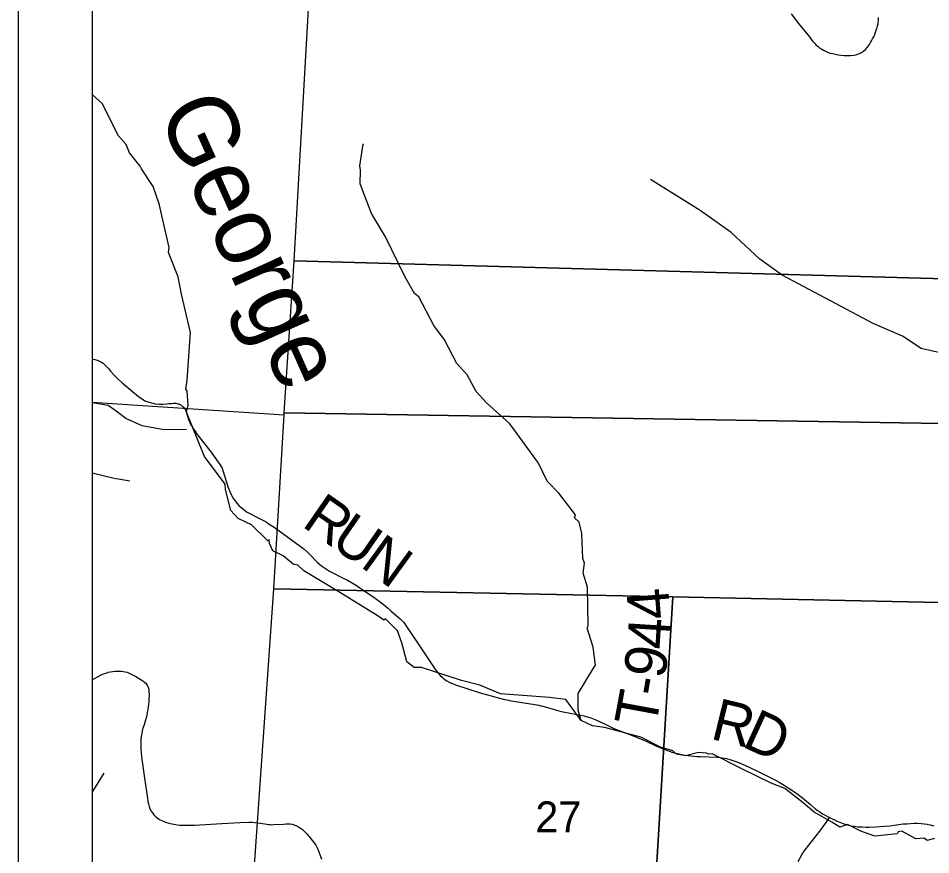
# Model space of a CAD drawing. Extents: x -2.1 to 31.9, y 6.3 to 28.3.
# Drawn here: x -0.066 to 1.171, y 22.391 to 23.525 of the extents above; entities that cross this region are included whole.
import ezdxf

# ---------------------------------------------------------------- set-up
doc = ezdxf.new("R2010")
doc.units = 0
for name, color, linetype in [('Default', 7, 'Continuous'), ('GM_X_County_Road', 7, 'Continuous'), ('GM_X_County_Road_Text', 7, 'Continuous'), ('GM_X_Minor_River', 7, 'Continuous'), ('GM_X_Minor_River_Text', 7, 'Continuous'), ('GM_X_Section', 7, 'Continuous'), ('GM_X_Section_Text', 7, 'Continuous'), ('GM_X_Township_Road', 7, 'Continuous'), ('GM_X_Township_Road_Text', 7, 'Continuous'), ('SH_Cut_Line', 7, 'Continuous'), ('SH_Data', 7, 'Continuous')]:
    doc.layers.add(name, color=color, linetype=linetype)

msp = doc.modelspace()

# ---------------------------------------------------------------- linework, layer by layer
at = {"layer": 'Default'}
for points in [[(0.0344, 26.1105), (0.0344, 20.444), (3.7533, 20.444), (3.8489, 20.5389), (3.9894, 20.6326), (4.16, 20.7203), (4.2895, 20.7662), (4.3023, 20.7658), (4.3091, 20.8714), (4.3751, 21.8979), (4.4168, 22.5238), (4.4383, 22.8067), (4.4651, 23.2405), (4.4901, 23.6442), (4.5473, 24.5954), (4.5667, 24.9084), (4.6032, 25.4816), (4.6286, 25.8765), (3.8625, 25.9158), (3.0763, 25.9555), (2.8034, 25.9683), (2.0757, 26.0047), (0.4641, 26.0883)], [(0.0344, 24.0467), (0.0344, 23.0048), (0.2947, 22.9877), (0.2949, 22.9906), (0.3083, 23.1964), (0.3317, 23.6098), (0.3588, 24.0351)]]:
    msp.add_lwpolyline(points, close=True, dxfattribs=at)
at = {"layer": 'GM_X_County_Road'}
for points in [[(0.0344, 23.0636), (0.0384, 23.0625), (0.0416, 23.0616), (0.0447, 23.0606), (0.0472, 23.0592), (0.0494, 23.0576), (0.0519, 23.0555), (0.0546, 23.0527), (0.057, 23.0501), (0.0596, 23.047), (0.0639, 23.0419), (0.0667, 23.039), (0.0695, 23.0364), (0.0755, 23.0313), (0.0976, 23.0127), (0.1022, 23.0094), (0.1062, 23.0069), (0.1102, 23.0054), (0.115, 23.0039), (0.1202, 23.0028), (0.1255, 23.0023), (0.1305, 23.0022), (0.1353, 23.0025), (0.1392, 23.0029), (0.1424, 23.0031), (0.1446, 23.0033), (0.1461, 23.0033), (0.1478, 23.0033), (0.1492, 23.0031), (0.1508, 23.0028), (0.1521, 23.0024), (0.1535, 23.0018), (0.1547, 23.0012), (0.1558, 23.0004), (0.1568, 22.9996), (0.1577, 22.9988), (0.1586, 22.9979), (0.1593, 22.9971), (0.1606, 22.9953), (0.1612, 22.9942), (0.1617, 22.993), (0.1625, 22.9909), (0.1631, 22.9884), (0.1637, 22.9858), (0.1646, 22.983), (0.1657, 22.9802), (0.167, 22.9772), (0.1685, 22.9741), (0.1704, 22.9708), (0.1725, 22.9677), (0.1747, 22.9645), (0.1771, 22.9611), (0.1957, 22.9369), (0.2063, 22.9222), (0.208, 22.9198), (0.2095, 22.9176), (0.2106, 22.9153), (0.2119, 22.9122), (0.2191, 22.8893), (0.2213, 22.8836), (0.2231, 22.8795), (0.2245, 22.8769), (0.2262, 22.8739), (0.2283, 22.871), (0.2308, 22.8678), (0.2334, 22.865), (0.2367, 22.8619), (0.24, 22.8592), (0.2439, 22.8564), (0.2483, 22.8539), (0.2598, 22.8481), (0.2652, 22.8455), (0.2678, 22.8441), (0.2707, 22.8422), (0.2759, 22.8388), (0.2811, 22.8355), (0.3167, 22.8095), (0.3213, 22.8062), (0.3258, 22.8025), (0.3294, 22.7989), (0.3401, 22.7876), (0.3455, 22.783), (0.3507, 22.7795), (0.3565, 22.776), (0.3626, 22.7727), (0.3696, 22.7691), (0.375, 22.7665), (0.3806, 22.7637), (0.386, 22.7605), (0.3915, 22.7571), (0.3973, 22.7533), (0.4101, 22.7448), (0.4165, 22.7404), (0.4218, 22.7365), (0.4274, 22.7324), (0.4312, 22.7293), (0.435, 22.726), (0.4395, 22.722), (0.4525, 22.7107), (0.4549, 22.7086), (0.4566, 22.7066), (0.4582, 22.7044), (0.4598, 22.7021), (0.4821, 22.6691), (0.4981, 22.6448), (0.5, 22.6421), (0.5021, 22.6395), (0.504, 22.6371), (0.5064, 22.6343), (0.5089, 22.6319), (0.5117, 22.6295), (0.5152, 22.6272), (0.5192, 22.6251), (0.5228, 22.6235), (0.5269, 22.6219), (0.5604, 22.6109), (0.5653, 22.6094), (0.5704, 22.608), (0.5937, 22.6019), (0.597, 22.6012), (0.6002, 22.6006), (0.6029, 22.6001), (0.6056, 22.5996), (0.6344, 22.5952), (0.6374, 22.5946), (0.6402, 22.594), (0.6426, 22.5934), (0.6455, 22.5926), (0.6502, 22.5913)], [(0.0344, 22.6287), (0.0469, 22.6352), (0.0501, 22.6366), (0.0534, 22.6377), (0.0564, 22.6387), (0.0595, 22.6394), (0.0624, 22.6398), (0.0653, 22.6402), (0.0685, 22.6403), (0.0714, 22.6403), (0.0743, 22.6402), (0.0768, 22.6399), (0.0794, 22.6395), (0.082, 22.6387), (0.0846, 22.6377), (0.0874, 22.6364), (0.0939, 22.6329), (0.0999, 22.6293), (0.1018, 22.6281), (0.1035, 22.627), (0.1055, 22.6254), (0.1072, 22.6238), (0.1087, 22.6219), (0.1098, 22.6202), (0.1106, 22.6187), (0.1111, 22.617), (0.1114, 22.615), (0.1116, 22.6122), (0.1117, 22.6091), (0.1115, 22.6018), (0.1113, 22.5985), (0.111, 22.5952), (0.1105, 22.5917), (0.11, 22.588), (0.1092, 22.5842), (0.1085, 22.5807), (0.1076, 22.5769), (0.1063, 22.5723), (0.1049, 22.5674), (0.1035, 22.5628), (0.1025, 22.5593), (0.1018, 22.5557), (0.1012, 22.5518), (0.1007, 22.5475), (0.1005, 22.5432), (0.1006, 22.5389), (0.1008, 22.5344), (0.1011, 22.5296), (0.1017, 22.524), (0.1057, 22.4952), (0.1094, 22.468), (0.1101, 22.4636), (0.1108, 22.4603), (0.1117, 22.457), (0.1128, 22.454), (0.1143, 22.4509), (0.1162, 22.448), (0.1183, 22.4454), (0.1202, 22.4435), (0.1229, 22.4415), (0.1261, 22.4394), (0.1298, 22.4374), (0.1339, 22.4356), (0.1385, 22.4341), (0.1427, 22.4331), (0.1478, 22.4322), (0.1529, 22.4316), (0.1586, 22.4313), (0.1644, 22.4314), (0.1732, 22.4317), (0.2103, 22.4339), (0.2348, 22.4352), (0.247, 22.4357), (0.2494, 22.4357), (0.2517, 22.4355), (0.2628, 22.434), (0.2739, 22.4324), (0.2759, 22.4322), (0.2779, 22.4321), (0.2803, 22.4322), (0.2941, 22.433), (0.2976, 22.4333), (0.3008, 22.4334), (0.3032, 22.4332), (0.3058, 22.4327), (0.3085, 22.4319), (0.3114, 22.4307), (0.3143, 22.4293), (0.3172, 22.4275), (0.3197, 22.4256), (0.3215, 22.424), (0.323, 22.4226), (0.3243, 22.4212), (0.3256, 22.4197), (0.327, 22.4181), (0.3282, 22.4167), (0.3296, 22.4149), (0.3367, 22.4057), (0.3377, 22.4042), (0.3387, 22.4025), (0.3396, 22.4008), (0.3405, 22.3988), (0.3456, 22.3852)], [(0.6502, 22.5913), (0.6673, 22.5864), (0.6705, 22.5856), (0.6732, 22.585), (0.7013, 22.5796), (0.7038, 22.579), (0.7062, 22.5783), (0.7086, 22.5775), (0.7107, 22.5768), (0.7129, 22.576), (0.7149, 22.5752), (0.7173, 22.5742), (0.7298, 22.5683), (0.7416, 22.5627), (0.7714, 22.5512), (0.7743, 22.55), (0.7777, 22.5487), (0.7811, 22.5472), (0.7848, 22.5456), (0.7997, 22.5387), (0.8062, 22.5358), (0.8121, 22.5335), (0.8168, 22.5317), (0.8218, 22.5301), (0.8259, 22.529), (0.83, 22.5281), (0.8339, 22.5273), (0.8379, 22.5266), (0.8422, 22.526), (0.8462, 22.5255), (0.8503, 22.5251), (0.8543, 22.5247), (0.8592, 22.5244), (0.8813, 22.5238), (0.884, 22.5236), (0.8864, 22.5233), (0.8888, 22.5229), (0.8942, 22.5218), (0.9004, 22.5201), (0.9069, 22.5179), (0.9131, 22.5154), (0.9202, 22.5124), (0.9271, 22.5091), (0.9344, 22.5055), (0.9572, 22.4942), (0.9616, 22.492), (0.9657, 22.4897), (0.9701, 22.4872), (0.9739, 22.4849), (0.9779, 22.4823), (0.9828, 22.479), (0.9897, 22.4743), (0.9975, 22.4684), (1.0026, 22.4641), (1.0082, 22.4595), (1.0143, 22.4543), (1.0152, 22.4536)], [(1.0152, 22.4536), (1.0179, 22.4516), (1.0208, 22.4495), (1.0233, 22.4478), (1.0252, 22.4466), (1.0338, 22.4419), (1.0443, 22.4368), (1.0491, 22.4349), (1.0535, 22.4332), (1.0585, 22.4318), (1.063, 22.4308), (1.0676, 22.43), (1.0725, 22.4294), (1.0783, 22.4292), (1.0832, 22.429), (1.0883, 22.429), (1.0969, 22.4293), (1.1022, 22.4296), (1.1086, 22.4301), (1.1159, 22.4308), (1.134, 22.4331), (1.139, 22.4335), (1.1439, 22.4339), (1.1486, 22.434), (1.1529, 22.434), (1.158, 22.4337), (1.1622, 22.4333), (1.1663, 22.4327), (1.1705, 22.4319), (1.1755, 22.4308)]]:
    msp.add_lwpolyline(points, dxfattribs=at)
at = {"layer": 'GM_X_Minor_River'}
msp.add_line((0.0344, 22.4758), (0.051, 22.502), dxfattribs=at)
for points in [[(0.6974, 22.5732), (0.6766, 22.602), (0.6543, 22.6046), (0.5881, 22.6094), (0.5602, 22.6211), (0.5352, 22.6275), (0.4808, 22.6453), (0.4709, 22.6452), (0.4611, 22.6528), (0.4543, 22.6787), (0.4486, 22.695), (0.4323, 22.7113), (0.43, 22.7094), (0.4236, 22.7139), (0.421, 22.7158), (0.3691, 22.748), (0.3215, 22.7764), (0.3132, 22.784), (0.3071, 22.7851), (0.2935, 22.7965), (0.2795, 22.8033), (0.275, 22.8135), (0.2746, 22.8189), (0.2731, 22.8166), (0.2507, 22.8386), (0.2326, 22.8473), (0.2227, 22.8579), (0.2152, 22.8867), (0.2148, 22.8936), (0.1868, 22.9311), (0.1856, 22.9342), (0.1625, 22.9911), (0.1648, 23.0006), (0.1636, 23.0204), (0.1614, 23.0227), (0.1632, 23.0345), (0.1677, 23.0991), (0.1559, 23.1511), (0.151, 23.1747), (0.1381, 23.2077), (0.1389, 23.2146), (0.1256, 23.2738), (0.1173, 23.297), (0.1017, 23.3213), (0.0998, 23.3247), (0.0851, 23.3429), (0.0809, 23.3543), (0.0703, 23.3657), (0.048, 23.4097), (0.0344, 23.4218)], [(0.6896, 22.8521), (0.6673, 22.8817), (0.6514, 22.898), (0.6396, 22.9223), (0.6033, 22.972), (0.6003, 22.9758), (0.5693, 23.0039), (0.5549, 23.0194), (0.5492, 23.03), (0.5428, 23.0418), (0.5288, 23.0573), (0.5121, 23.0892), (0.4977, 23.1086), (0.4773, 23.1477), (0.4716, 23.1522), (0.4583, 23.175), (0.4322, 23.2289), (0.4133, 23.2604), (0.3977, 23.3007), (0.3981, 23.3193), (0.3973, 23.3254), (0.4019, 23.3546), (0.403, 23.355)], [(1.1915, 23.0701), (1.1584, 23.0776), (1.1329, 23.0944), (1.0933, 23.1116), (0.9698, 23.177), (0.9395, 23.1985), (0.9009, 23.235), (0.8587, 23.2648), (0.7912, 23.3069)], [(0.1625, 22.9674), (0.1296, 22.9677), (0.1026, 22.9727), (0.0802, 22.9829), (0.0673, 22.9928), (0.0565, 23.0004), (0.0351, 23.0041), (0.0344, 23.0044)], [(1.1761, 22.4132), (1.1663, 22.4109), (1.1625, 22.4139), (1.1508, 22.4128), (1.1319, 22.4234), (1.127, 22.4226), (1.1255, 22.4199), (1.0952, 22.4164), (1.0763, 22.4232), (1.0582, 22.4323), (1.048, 22.4288), (1.037, 22.4357), (1.0132, 22.4489), (0.9984, 22.4618), (0.9735, 22.4811), (0.9549, 22.4883), (0.916, 22.5076), (0.8748, 22.528), (0.8698, 22.5276), (0.8672, 22.5291), (0.8566, 22.5302), (0.8389, 22.5256), (0.8264, 22.5279), (0.8218, 22.5324), (0.8048, 22.537), (0.7783, 22.551), (0.7288, 22.5641), (0.7129, 22.566), (0.6974, 22.5732), (0.6933, 22.5876), (0.6932, 22.61), (0.714, 22.6443), (0.717, 22.6485), (0.7136, 22.6728), (0.7056, 22.6986), (0.7068, 22.7013), (0.706, 22.7541), (0.7003, 22.7731), (0.7021, 22.7868), (0.6995, 22.7929), (0.6983, 22.8267), (0.6945, 22.8423), (0.6885, 22.8483), (0.6896, 22.8521)]]:
    msp.add_lwpolyline(points, dxfattribs=at)
at = {"layer": 'GM_X_Section'}
for points in [[(1.3641, 23.5904), (1.3376, 23.1681), (0.3083, 23.1964), (0.3317, 23.6098)], [(0.3083, 23.1964), (1.3376, 23.1681), (1.3254, 22.9735), (0.2949, 22.9906)], [(0.2947, 22.9877), (0.2949, 22.9906), (1.3254, 22.9735), (1.3102, 22.7307), (0.8218, 22.7408), (0.2809, 22.7519)], [(0.8218, 22.7408), (0.7728, 21.931), (0.2247, 21.9507), (0.2809, 22.7519)], [(1.3102, 22.7307), (1.2591, 21.9158), (0.7728, 21.931), (0.8218, 22.7408)]]:
    msp.add_lwpolyline(points, close=True, dxfattribs=at)
at = {"layer": 'GM_X_Township_Road'}
for points in [[(0.9818, 23.5312), (0.9921, 23.5181), (1.0068, 23.5), (1.0098, 23.4959), (1.0116, 23.4937), (1.0136, 23.4914), (1.0161, 23.4889), (1.0185, 23.4869), (1.021, 23.4849), (1.0236, 23.4833), (1.0257, 23.482), (1.0278, 23.481), (1.0303, 23.4797), (1.0322, 23.479), (1.035, 23.4781), (1.0381, 23.4773), (1.0423, 23.4765), (1.0459, 23.4759), (1.0494, 23.4754), (1.054, 23.4749), (1.0588, 23.4746), (1.0631, 23.4747), (1.0674, 23.4752), (1.0711, 23.4761), (1.0745, 23.4774), (1.0773, 23.4788), (1.0799, 23.4806), (1.0827, 23.483), (1.0852, 23.4857), (1.0867, 23.4878), (1.0881, 23.4899), (1.0895, 23.4922), (1.091, 23.4947), (1.0924, 23.4974), (1.0939, 23.5003), (1.0952, 23.5035), (1.0978, 23.5103), (1.0984, 23.5124), (1.0991, 23.5152), (1.0998, 23.5178), (1.1001, 23.5199), (1.1004, 23.5217), (1.1005, 23.5235), (1.1006, 23.5261)], [(0.0344, 22.909), (0.0625, 22.9024), (0.0666, 22.9015), (0.0705, 22.9008), (0.0855, 22.8983)], [(0.9916, 22.3823), (0.997, 22.3921), (0.9982, 22.394), (0.9993, 22.3959), (1.0009, 22.3981), (1.0209, 22.4235), (1.0294, 22.4353), (1.0338, 22.4419)]]:
    msp.add_lwpolyline(points, dxfattribs=at)
at = {"layer": 'SH_Cut_Line'}
msp.add_lwpolyline([(0.0344, 27.244), (0.0344, 20.444), (3.7533, 20.444)], dxfattribs=at)
at = {"layer": 'SH_Data'}
for p, q in [((-0.0656, 27.344), (-0.0656, 20.344)), ((0.0344, 27.244), (0.0344, 20.444))]:
    msp.add_line(p, q, dxfattribs=at)

# ---------------------------------------------------------------- texts
at = {"layer": 'GM_X_County_Road_Text'}
for s, rotation, p in [('R', 325.307, (0.3172, 22.8376)), ('U', 325.2799, (0.3556, 22.8111)), ('N', 324.1181, (0.3965, 22.7828)), ('R', 346.3358, (0.871, 22.5489)), ('D', 335.3756, (0.9136, 22.5388))]:
    msp.add_text(s, height=0.0568, rotation=rotation, dxfattribs=at).set_placement(p)
at = {"layer": 'GM_X_Minor_River_Text'}
msp.add_text('George', height=0.09469, rotation=294.1351, dxfattribs=at).set_placement((0.1225, 23.399))
at = {"layer": 'GM_X_Section_Text'}
msp.add_text('27', height=0.04186, rotation=0, dxfattribs=at).set_placement((0.6353, 22.4218))
at = {"layer": 'GM_X_Township_Road_Text'}
for s, rotation, p in [('4', 94.394, (0.8185, 22.7124)), ('4', 86.3482, (0.8163, 22.6687)), ('9', 81.0918, (0.8103, 22.6285)), ('-', 79.8371, (0.8059, 22.6042)), ('T', 79.5276, (0.7981, 22.5621))]:
    msp.add_text(s, height=0.0568, rotation=rotation, dxfattribs=at).set_placement(p)

doc.saveas('drawing.dxf')
